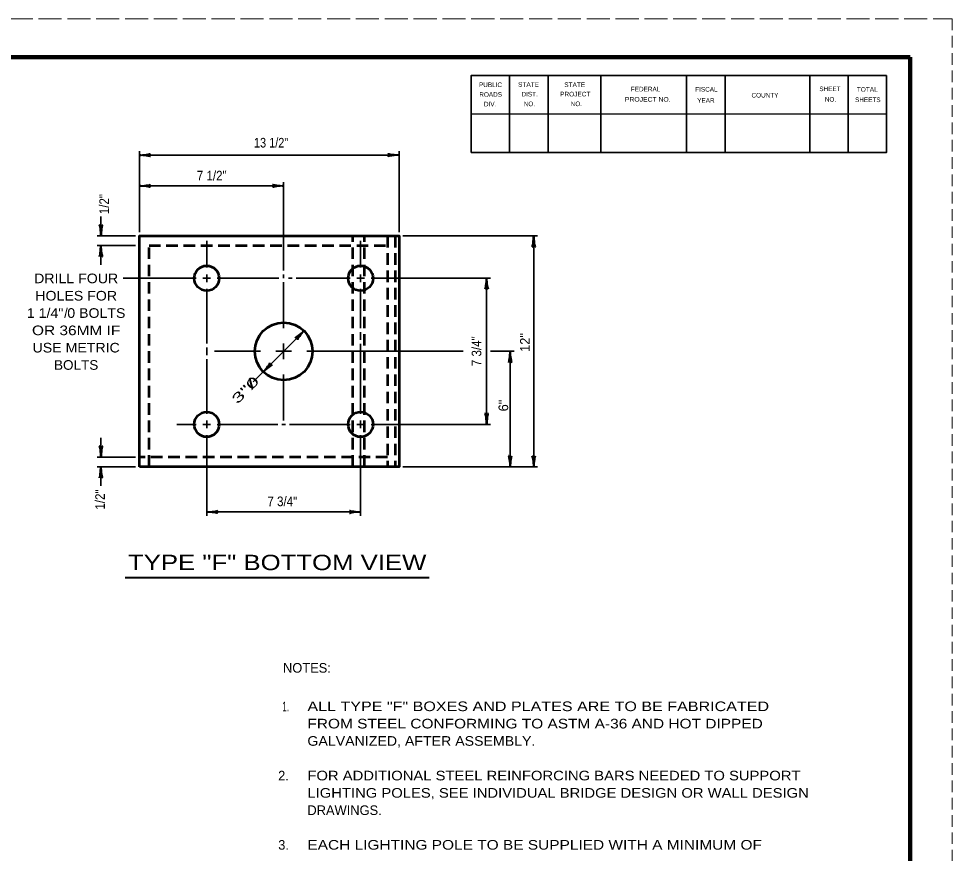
# Model space of a CAD drawing. Extents: x -1 to 679, y 0 to 440.
# Drawn here: x 436 to 678.6, y 222.7 to 439.6 of the extents above; entities that cross this region are included whole.
import ezdxf
from ezdxf.enums import TextEntityAlignment as Align

# ---------------------------------------------------------------- set-up
doc = ezdxf.new("R2010")
doc.units = 0
doc.linetypes.add('LONG_DASHED', pattern=[7.5, 6, -1.5])
doc.linetypes.add('MEDIUM_DASHED', pattern=[4.5, 3, -1.5])
doc.layers.add('1', color=7, linetype='Continuous', lineweight=53)
doc.layers.add('61', color=7, linetype='Continuous', lineweight=35)

msp = doc.modelspace()

# ---------------------------------------------------------------- linework, layer by layer
at = {"layer": '1', "linetype": 'MEDIUM_DASHED', "lineweight": 13}
msp.add_line((678.644, 439.629), (678.624, -0.391), dxfattribs=at)
at = {"layer": '1', "lineweight": 35}
for p, q in [((467.344, 384.171), (467.344, 405.171)), ((467.344, 404.171), (534.844, 404.171)), ((534.844, 384.171), (534.844, 405.171)), ((504.844, 396.171), (467.344, 396.171)), ((504.844, 374.171), (504.844, 397.171)), ((457.344, 383.171), (457.344, 388.171)), ((466.344, 383.171), (456.344, 383.171)), ((484.844, 374.921), (484.844, 381.921)), ((524.844, 374.921), (524.844, 381.921)), ((535.844, 383.171), (570.844, 383.171)), ((569.844, 383.171), (569.844, 323.171)), ((466.344, 380.671), (456.344, 380.671)), ((457.344, 380.671), (457.344, 375.671)), ((482.094, 372.171), (463.094, 372.171)), ((483.844, 372.171), (485.844, 372.171)), ((484.844, 371.171), (484.844, 373.171)), ((487.594, 372.171), (503.594, 372.171)), ((504.844, 372.171), (504.844, 373.171)), ((507.094, 372.171), (506.094, 372.171)), ((522.094, 372.171), (508.094, 372.171)), ((523.844, 372.171), (525.844, 372.171)), ((524.844, 371.171), (524.844, 373.171)), ((527.594, 372.171), (558.594, 372.171)), ((557.594, 372.171), (557.594, 334.171)), ((484.844, 369.421), (484.844, 355.171)), ((504.844, 359.171), (504.844, 371.171)), ((524.844, 369.421), (524.844, 359.157)), ((496.921, 345.249), (510.147, 358.474)), ((524.844, 358.157), (524.844, 356.157)), ((504.844, 351.171), (504.844, 355.171)), ((524.844, 355.157), (524.844, 336.921)), ((484.844, 354.171), (484.844, 352.171)), ((498.844, 353.171), (486.844, 353.171)), ((502.844, 353.171), (506.844, 353.171)), ((510.844, 353.171), (551.478, 353.171)), ((558.594, 353.171), (564.719, 353.171)), ((563.719, 323.171), (563.719, 353.171)), ((484.844, 351.171), (484.844, 336.921)), ((504.844, 347.171), (504.844, 335.171)), ((484.844, 333.171), (484.844, 335.171)), ((524.844, 333.171), (524.844, 335.171)), ((482.094, 334.171), (477.094, 334.171)), ((483.844, 334.171), (485.844, 334.171)), ((487.594, 334.171), (503.344, 334.171)), ((504.344, 334.171), (505.344, 334.171)), ((506.344, 334.171), (522.094, 334.171)), ((523.844, 334.171), (525.844, 334.171)), ((527.594, 334.171), (558.594, 334.171)), ((457.344, 325.671), (457.344, 330.671)), ((484.844, 331.421), (484.844, 310.421)), ((524.844, 331.421), (524.844, 310.421)), ((466.344, 325.671), (456.344, 325.671)), ((466.344, 323.171), (456.344, 323.171)), ((457.344, 323.171), (457.344, 318.171)), ((535.844, 323.171), (570.844, 323.171)), ((484.844, 311.421), (524.844, 311.421))]:
    msp.add_line(p, q, dxfattribs=at)
at = {"layer": '1', "linetype": 'MEDIUM_DASHED'}
for p, q in [((522.844, 323.171), (522.844, 383.171)), ((525.844, 323.171), (525.844, 383.171)), ((531.844, 383.171), (531.844, 323.171)), ((533.844, 383.171), (533.844, 323.171)), ((469.844, 380.671), (531.844, 380.671)), ((469.844, 323.171), (469.844, 380.671)), ((531.844, 325.671), (467.344, 325.671))]:
    msp.add_line(p, q, dxfattribs=at)
at = {"layer": '1', "lineweight": 40}
msp.add_line((463.648, 294.371), (542.662, 294.371), dxfattribs=at)
at = {"layer": '1'}
msp.add_lwpolyline([(467.344, 323.171), (467.344, 383.171), (534.844, 383.171), (534.844, 323.171)], close=True, dxfattribs=at)
for centre, radius in [((484.844, 372.171), 3.25), ((524.844, 372.171), 3.25), ((504.844, 353.171), 7.5), ((484.844, 334.171), 3.25), ((524.844, 334.171), 3.25)]:
    msp.add_circle(centre, radius, dxfattribs=at)
at = {"layer": '1', "lineweight": 40}
for centre, major_axis, ratio, start_param, end_param in [((468.464, 403.959), (-1.756, 0.176), 0.07063, 3.1407148, 5.41811), ((468.435, 404.447), (-1.786, -0.156), 0.122415, 0.8963533, 3.1415927), ((533.752, 403.895), (1.786, 0.156), 0.122415, 0.8963533, 3.1415927), ((533.723, 404.383), (1.756, -0.176), 0.07063, 3.1407148, 5.41811), ((468.464, 395.959), (-1.756, 0.176), 0.07063, 3.1407148, 5.41811), ((468.464, 395.959), (-1.756, 0.176), 0.07063, 3.1407148, 5.41811), ((468.435, 396.447), (-1.786, -0.156), 0.122415, 0.8963533, 3.1415927), ((468.435, 396.447), (-1.786, -0.156), 0.122415, 0.8963533, 3.1415927), ((503.752, 395.895), (1.786, 0.156), 0.122415, 0.8963533, 3.1415927), ((503.723, 396.383), (1.756, -0.176), 0.07063, 3.1407148, 5.41811), ((457.067, 384.262), (0.156, -1.786), 0.122415, 0.8963533, 3.1415927), ((457.067, 384.262), (0.156, -1.786), 0.122415, 0.8963533, 3.1415927), ((457.555, 384.292), (-0.176, -1.756), 0.07063, 3.1407148, 5.41811), ((457.555, 384.292), (-0.176, -1.756), 0.07063, 3.1407148, 5.41811), ((569.632, 382.051), (0.176, 1.756), 0.07063, 3.1407148, 5.41811), ((569.632, 382.051), (0.176, 1.756), 0.07063, 3.1407148, 5.41811), ((570.12, 382.08), (-0.156, 1.786), 0.122415, 0.8963533, 3.1415927), ((570.12, 382.08), (-0.156, 1.786), 0.122415, 0.8963533, 3.1415927), ((457.132, 379.551), (0.176, 1.756), 0.07063, 3.1407148, 5.41811), ((457.132, 379.551), (0.176, 1.756), 0.07063, 3.1407148, 5.41811), ((457.62, 379.58), (-0.156, 1.786), 0.122415, 0.8963533, 3.1415927), ((457.62, 379.58), (-0.156, 1.786), 0.122415, 0.8963533, 3.1415927), ((557.382, 371.051), (0.176, 1.756), 0.07063, 3.1407148, 5.41811), ((557.382, 371.051), (0.176, 1.756), 0.07063, 3.1407148, 5.41811), ((557.87, 371.08), (-0.156, 1.786), 0.122415, 0.8963533, 3.1415927), ((557.87, 371.08), (-0.156, 1.786), 0.122415, 0.8963533, 3.1415927), ((509.205, 357.832), (1.366, 1.118), 0.07063, 3.1407148, 5.41811), ((509.205, 357.832), (1.366, 1.118), 0.07063, 3.1407148, 5.41811), ((509.571, 357.507), (1.152, 1.373), 0.122415, 0.8963533, 3.1415927), ((509.571, 357.507), (1.152, 1.373), 0.122415, 0.8963533, 3.1415927), ((563.507, 352.051), (0.176, 1.756), 0.07063, 3.1407148, 5.41811), ((563.507, 352.051), (0.176, 1.756), 0.07063, 3.1407148, 5.41811), ((563.995, 352.08), (-0.156, 1.786), 0.122415, 0.8963533, 3.1415927), ((563.995, 352.08), (-0.156, 1.786), 0.122415, 0.8963533, 3.1415927), ((500.116, 348.835), (-1.152, -1.373), 0.122415, 0.8963533, 3.1415927), ((500.482, 348.51), (-1.366, -1.118), 0.07063, 3.1407148, 5.41811), ((557.317, 335.262), (0.156, -1.786), 0.122415, 0.8963533, 3.1415927), ((557.317, 335.262), (0.156, -1.786), 0.122415, 0.8963533, 3.1415927), ((557.805, 335.292), (-0.176, -1.756), 0.07063, 3.1407148, 5.41811), ((557.805, 335.292), (-0.176, -1.756), 0.07063, 3.1407148, 5.41811), ((457.067, 326.762), (0.156, -1.786), 0.122415, 0.8963533, 3.1415927), ((457.067, 326.762), (0.156, -1.786), 0.122415, 0.8963533, 3.1415927), ((457.555, 326.792), (-0.176, -1.756), 0.07063, 3.1407148, 5.41811), ((457.555, 326.792), (-0.176, -1.756), 0.07063, 3.1407148, 5.41811), ((563.442, 324.262), (0.156, -1.786), 0.122415, 0.8963533, 3.1415927), ((563.442, 324.262), (0.156, -1.786), 0.122415, 0.8963533, 3.1415927), ((563.93, 324.292), (-0.176, -1.756), 0.07063, 3.1407148, 5.41811), ((563.93, 324.292), (-0.176, -1.756), 0.07063, 3.1407148, 5.41811), ((569.567, 324.262), (0.156, -1.786), 0.122415, 0.8963533, 3.1415927), ((570.055, 324.292), (-0.176, -1.756), 0.07063, 3.1407148, 5.41811), ((457.132, 322.051), (0.176, 1.756), 0.07063, 3.1407148, 5.41811), ((457.62, 322.08), (-0.156, 1.786), 0.122415, 0.8963533, 3.1415927), ((485.964, 311.209), (-1.756, 0.176), 0.07063, 3.1407148, 5.41811), ((485.964, 311.209), (-1.756, 0.176), 0.07063, 3.1407148, 5.41811), ((485.935, 311.697), (-1.786, -0.156), 0.122415, 0.8963533, 3.1415927), ((485.935, 311.697), (-1.786, -0.156), 0.122415, 0.8963533, 3.1415927), ((523.752, 311.145), (1.786, 0.156), 0.122415, 0.8963533, 3.1415927), ((523.723, 311.633), (1.756, -0.176), 0.07063, 3.1407148, 5.41811)]:
    msp.add_ellipse(centre, major_axis=major_axis, ratio=ratio, start_param=start_param, end_param=end_param, dxfattribs=at)
at = {"layer": '61', "linetype": 'LONG_DASHED', "lineweight": 13}
msp.add_line((-1.376, 439.629), (678.644, 439.629), dxfattribs=at)
at = {"layer": '61', "lineweight": 158}
msp.add_line((667.664, 429.629), (667.684, 9.589), dxfattribs=at)
at = {"layer": '61'}
for p, q in [((563.584, 424.869), (563.584, 404.869)), ((573.584, 424.869), (573.584, 404.869)), ((587.264, 424.869), (587.264, 404.869)), ((609.584, 424.869), (609.584, 404.869)), ((619.584, 424.869), (619.584, 404.869)), ((641.564, 424.889), (641.564, 404.889)), ((651.564, 424.889), (651.564, 404.889)), ((661.584, 414.849), (553.564, 414.869))]:
    msp.add_line(p, q, dxfattribs=at)
at = {"layer": '61', "lineweight": 158}
msp.add_lwpolyline([(667.664, 429.629), (28.624, 429.629), (28.624, 9.609)], dxfattribs=at)
at = {"layer": '61'}
for points in [[(661.564, 424.889), (553.584, 424.869), (553.584, 404.869)], [(661.564, 424.889), (661.564, 404.889), (553.584, 404.869)]]:
    msp.add_lwpolyline(points, dxfattribs=at)

# ---------------------------------------------------------------- texts
at = {"layer": '1'}
for s, height, width, p in [('13 1/2"', 2.5, 0.85, (501.578, 406.143)), ('7 1/2"', 2.5, 0.9, (486.151, 397.593)), ('DRILL FOUR', 2.5, 1.1, (450.912, 370.873)), ('HOLES FOR', 2.5, 1.1, (450.913, 366.373)), ('1 1/4" 0 BOLTS', 2.5, 1.1, (450.912, 361.873)), ('OR 36MM IF', 2.5, 1.2, (450.912, 357.373)), ('USE METRIC', 2.5, 1.1, (450.913, 352.873)), ('BOLTS', 2.5, 1.05, (450.912, 348.373)), ('7 3/4"', 2.5, 0.9, (504.497, 312.926)), ('TYPE "F" BOTTOM VIEW', 4, 1.25, (503.164, 296.304)), ('1.', 2.5, 0.65, (505.384, 259.623))]:
    msp.add_text(s, height=height, dxfattribs=dict(at, width=width)).set_placement(p, align=Align.CENTER)
for s, rotation, width, p in [('1/2"', 90, 0.9, (459.434, 391.435)), ('7 3/4"', 90, 0.9, (556.218, 353.195)), ('3"0', 45, 1.7, (495.763, 342.247)), ('/', 45, 2.3, (497.292, 343.822)), ('1/2"', 90, 0.9, (458.373, 314.651))]:
    msp.add_text(s, height=2.5, rotation=rotation, dxfattribs=dict(at, width=width)).set_placement(p, align=Align.CENTER)
for s, p in [('/', (448.266, 361.87)), ('NOTES:', (510.895, 269.655)), ('2.', (504.808, 241.643)), ('3.', (504.821, 223.647))]:
    msp.add_text(s, height=2.5, dxfattribs=at).set_placement(p, align=Align.CENTER)
for s, p in [('12"', (568.808, 355.471)), ('6"', (563.196, 339.082))]:
    msp.add_text(s, height=2.5, rotation=90, dxfattribs=at).set_placement(p, align=Align.CENTER)
for s, width, p in [('ALL TYPE "F" BOXES AND PLATES ARE TO BE FABRICATED', 1.25, (511.018, 259.659)), ('FROM STEEL CONFORMING TO ASTM A-36 AND HOT DIPPED', 1.2, (511.018, 255.159)), ('GALVANIZED, AFTER ASSEMBLY.', 1.1, (511.018, 250.659)), ('FOR ADDITIONAL STEEL REINFORCING BARS NEEDED TO SUPPORT', 1.15, (511.018, 241.659)), ('LIGHTING POLES, SEE INDIVIDUAL BRIDGE DESIGN OR WALL DESIGN', 1.15, (511.018, 237.159)), ('EACH LIGHTING POLE TO BE SUPPLIED WITH A MINIMUM OF', 1.2, (511.018, 223.659))]:
    msp.add_text(s, height=2.5, dxfattribs=dict(at, width=width)).set_placement(p)
msp.add_text('DRAWINGS.', height=2.5, dxfattribs=at).set_placement((511.018, 232.659))
at = {"layer": '61'}
for s, rotation, p in [('PUBLIC', 0.033, (555.624, 421.849)), ('ROADS', 0.124, (555.704, 419.329)), ('DIST.', 0.056, (566.664, 419.409)), ('FEDERAL', 0.007, (595.084, 420.729)), ('FISCAL', 359.942, (611.824, 420.669)), ('COUNTY', 0.069, (626.444, 419.129)), ('SHEET', 0.059, (644.084, 420.789)), ('DIV.', 359.932, (556.904, 416.829)), ('YEAR', 0.105, (612.344, 417.769)), ('SHEETS', 359.959, (653.364, 417.949))]:
    msp.add_text(s, height=1.201, rotation=rotation, dxfattribs=at).set_placement(p)
for s, rotation, width, p in [('STATE', 0.059, 1.05, (565.784, 421.909)), ('STATE', 0.059, 1.05, (577.784, 421.849)), ('PROJECT', 359.908, 1.05, (576.704, 419.429)), ('TOTAL', 359.926, 1.05, (653.824, 420.649)), ('NO.', 359.852, 0.95, (567.244, 416.889)), ('NO.', 0.225, 0.95, (579.444, 416.889)), ('PROJECT NO.', 359.922, 1.1, (593.544, 418.069)), ('NO.', 359.852, 0.95, (645.504, 418.069))]:
    msp.add_text(s, height=1.201, rotation=rotation, dxfattribs=dict(at, width=width)).set_placement(p)

doc.saveas('drawing.dxf')
